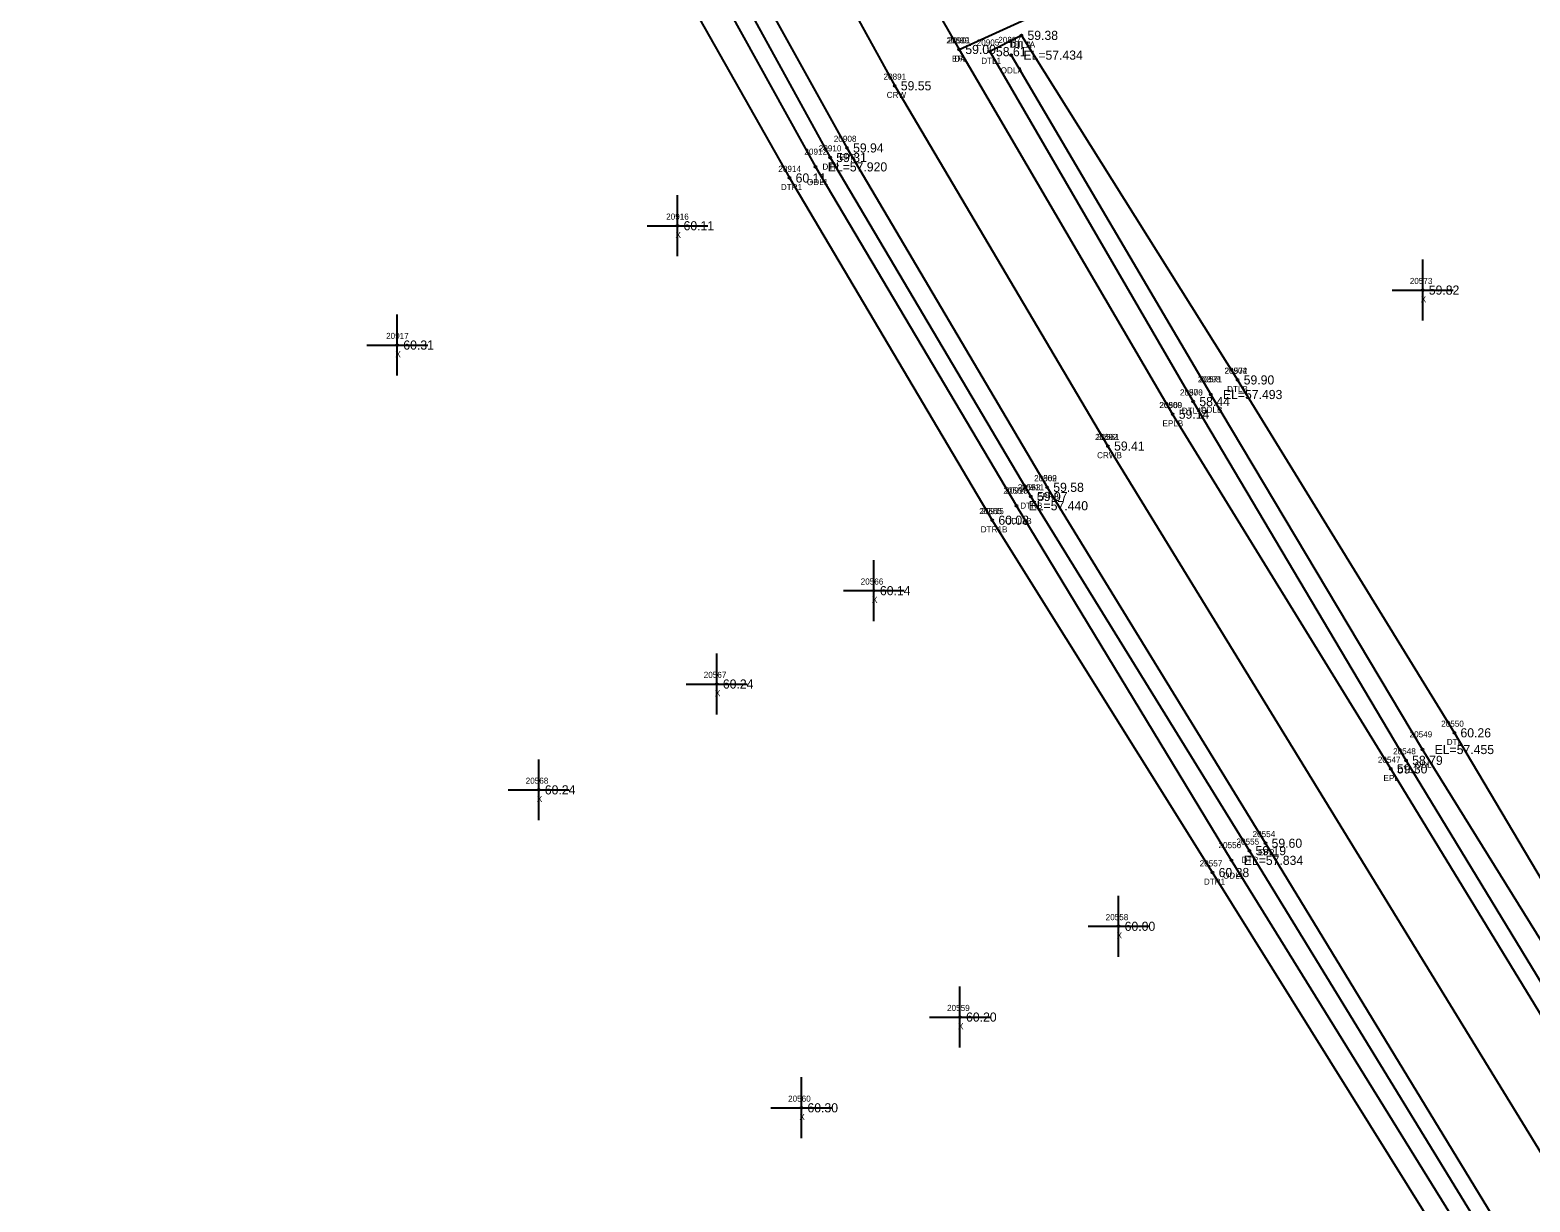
# Model space of a CAD drawing. Extents: x 2396547 to 2397655, y 770185 to 772649.
# Drawn here: x 2397093.2 to 2397339.4, y 770747.4 to 770939.8 of the extents above; entities that cross this region are included whole.
import ezdxf

# ---------------------------------------------------------------- set-up
doc = ezdxf.new("R2010")
doc.units = 0
for name, color, linetype in [('RD_DTM_BkLn1', 7, 'Continuous'), ('RD_EX_Driveway', 7, 'Continuous'), ('RD_EX_Driveway_txCode', 7, 'Continuous'), ('RD_EX_H2O', 7, 'Continuous'), ('RD_EX_H2O_txCode', 7, 'Continuous'), ('RD_EX_Misc', 7, 'Continuous'), ('RD_EX_Misc_txCode', 7, 'Continuous'), ('RD_EX_Road', 7, 'Continuous'), ('RD_EX_Road_txCode', 7, 'Continuous'), ('RD_EX_TX_Driveway_ELEV', 7, 'Continuous'), ('RD_EX_TX_H2O_ELEV', 7, 'Continuous'), ('RD_EX_TX_Misc_ELEV', 7, 'Continuous'), ('RD_EX_TX_Road_ELEV', 7, 'Continuous'), ('RD_HC_Survey_ELEV', 7, 'Continuous'), ('RD_HC_Survey_txCode', 7, 'Continuous'), ('RD_SMD_Locator', 7, 'Continuous')]:
    doc.layers.add(name, color=color, linetype=linetype)

msp = doc.modelspace()

# ---------------------------------------------------------------- linework, layer by layer
at = {"layer": 'RD_DTM_BkLn1'}
for points in [[(2397104.78, 771217.07), (2397119.02, 771175.87), (2397143.13, 771113.88), (2397170.45, 771052.64), (2397197.01, 770999.9), (2397235.12, 770930.63), (2397270.14, 770871.5)], [(2397565.46, 770206.19), (2397547.69, 770280.33), (2397528.11, 770352.94), (2397504.84, 770424.66), (2397476.69, 770499.34), (2397447.19, 770566.69), (2397412.23, 770635.13), (2397363.03, 770719.95), (2397270.14, 770871.5)]]:
    msp.add_lwpolyline(points, dxfattribs=at)
at = {"layer": 'RD_EX_Driveway'}
msp.add_line((2397245.72, 770936.59), (2397279.64, 770952.05), dxfattribs=at)
at = {"layer": 'RD_EX_H2O'}
for p, q in [((2397255.92, 770938.9), (2397291.42, 770882.36)), ((2397254.25, 770935.66), (2397287.01, 770879.96))]:
    msp.add_line(p, q, dxfattribs=at)
for points in [[(2397108.85, 771101.86), (2397130.27, 771108.67), (2397157.99, 771046.03), (2397184.53, 770991.63), (2397224.53, 770918.86), (2397257.48, 770863.23)], [(2397126.28, 771104.16), (2397151.7, 771043.04), (2397181.8, 770990.14), (2397222.13, 770917.32), (2397255.11, 770861.71)], [(2397108.85, 771101.86), (2397123.52, 771093.58), (2397147.97, 771040.86), (2397177.5, 770986.79), (2397217.86, 770915.5), (2397251.15, 770859.33)], [(2397255.92, 770938.9), (2397250.75, 770936.23), (2397284.14, 770878.8)], [(2397586.15, 770211.51), (2397567.31, 770287.61), (2397548.79, 770357.79), (2397525.19, 770434.22), (2397495.53, 770510.39), (2397465.51, 770576.5), (2397430.55, 770645.5), (2397380.29, 770734.7), (2397327.01, 770824.44), (2397291.42, 770882.36)], [(2397579.43, 770209.93), (2397561.1, 770285.3), (2397543.19, 770356.19), (2397518.98, 770431.67), (2397489.88, 770507.8), (2397460.56, 770573.86), (2397425.02, 770642.83), (2397373.6, 770730.3), (2397319.08, 770819.92), (2397284.14, 770878.8)], [(2397583.73, 770210.91), (2397565.2, 770287.05), (2397546.34, 770357.13), (2397522.25, 770433.23), (2397493.26, 770509.76), (2397463.19, 770575.43), (2397428.34, 770644.33), (2397377.24, 770732.42), (2397321.77, 770821.7), (2397287.01, 770879.96)], [(2397428.38, 770563.87), (2397397.36, 770626.2), (2397348.29, 770710.09), (2397290.43, 770803.51), (2397255.11, 770861.71)], [(2397432.83, 770561.85), (2397399.16, 770627.27), (2397350.75, 770711.42), (2397293.36, 770805.09), (2397257.48, 770863.23)], [(2397432.83, 770561.85), (2397426.86, 770559.56), (2397394.23, 770624.59), (2397345.55, 770708.21), (2397287.31, 770801.51), (2397251.15, 770859.33)]]:
    msp.add_lwpolyline(points, dxfattribs=at)
at = {"layer": 'RD_EX_Misc'}
for p, q in [((2397199.46, 770902.66), (2397199.46, 770912.66)), ((2397194.46, 770907.66), (2397204.46, 770907.66)), ((2397321.81, 770892.1), (2397321.81, 770902.1)), ((2397316.81, 770897.1), (2397326.81, 770897.1)), ((2397153.45, 770883.08), (2397153.45, 770893.08)), ((2397148.45, 770888.08), (2397158.45, 770888.08)), ((2397231.7, 770842.77), (2397231.7, 770852.77)), ((2397226.7, 770847.77), (2397236.7, 770847.77)), ((2397205.91, 770827.45), (2397205.91, 770837.45)), ((2397200.91, 770832.45), (2397210.91, 770832.45)), ((2397176.68, 770810.08), (2397176.68, 770820.08)), ((2397171.68, 770815.08), (2397181.68, 770815.08)), ((2397271.88, 770787.69), (2397271.88, 770797.69)), ((2397266.88, 770792.69), (2397276.88, 770792.69)), ((2397245.84, 770772.79), (2397245.84, 770782.79)), ((2397240.84, 770777.79), (2397250.84, 770777.79)), ((2397219.8, 770757.9), (2397219.8, 770767.9)), ((2397214.8, 770762.9), (2397224.8, 770762.9))]:
    msp.add_line(p, q, dxfattribs=at)
at = {"layer": 'RD_EX_Road'}
for points in [[(2397113.76, 771228.75), (2397130.87, 771177.98), (2397154.19, 771118.49), (2397170.38, 771081.25), (2397178.53, 771063.49), (2397207.96, 771004.56), (2397238.54, 770949.11), (2397245.72, 770936.59), (2397280.76, 770876.73)], [(2397093.16, 771212.62), (2397108.35, 771171.65), (2397122.66, 771133.29), (2397131.66, 771109.5), (2397159.86, 771046.96), (2397187.02, 770992.86), (2397227.29, 770920.43), (2397260.16, 770864.73)], [(2397576.88, 770209.21), (2397558.85, 770284.47), (2397539.93, 770354.87), (2397515.81, 770430.13), (2397486.97, 770506.75), (2397457.82, 770572.7), (2397422.37, 770641.75), (2397371.16, 770729.12), (2397316.57, 770818.52), (2397280.76, 770876.73)], [(2397553.19, 770205.48), (2397535.12, 770280.96), (2397517, 770349.24), (2397493.4, 770422.78), (2397467.13, 770492.9), (2397441.16, 770551.74), (2397436.66, 770561.67), (2397402.21, 770629.28), (2397353, 770712.83), (2397296, 770806.32), (2397260.16, 770864.73)]]:
    msp.add_lwpolyline(points, dxfattribs=at)
at = {"layer": 'RD_SMD_Locator'}
for centre in [(2397255.92, 770938.9), (2397255.92, 770938.9), (2397245.72, 770936.59), (2397245.72, 770936.59), (2397250.75, 770936.23), (2397254.25, 770935.66), (2397235.12, 770930.63), (2397227.29, 770920.43), (2397224.53, 770918.86), (2397217.86, 770915.5), (2397222.13, 770917.32), (2397199.46, 770907.66), (2397321.81, 770897.1), (2397153.45, 770888.08), (2397291.42, 770882.36), (2397291.42, 770882.36), (2397284.14, 770878.8), (2397284.14, 770878.8), (2397287.01, 770879.96), (2397287.01, 770879.96), (2397280.76, 770876.73), (2397280.76, 770876.73), (2397270.14, 770871.5), (2397270.14, 770871.5), (2397260.16, 770864.73), (2397260.16, 770864.73), (2397255.11, 770861.71), (2397255.11, 770861.71), (2397257.48, 770863.23), (2397257.48, 770863.23), (2397251.15, 770859.33), (2397251.15, 770859.33), (2397231.7, 770847.77), (2397205.91, 770832.45), (2397327.01, 770824.44), (2397321.77, 770821.7), (2397319.08, 770819.92), (2397316.57, 770818.52), (2397176.68, 770815.08), (2397293.36, 770805.09), (2397296, 770806.32), (2397290.43, 770803.51), (2397287.31, 770801.51), (2397271.88, 770792.69), (2397245.84, 770777.79), (2397219.8, 770762.9)]:
    msp.add_circle(centre, 0.15, dxfattribs=at)

# ---------------------------------------------------------------- texts
at = {"layer": 'RD_EX_Driveway_txCode'}
for s, p in [('20901', (2397243.85, 770937.59)), ('DA', (2397244.93, 770934.59))]:
    msp.add_text(s, height=1, dxfattribs=at).set_placement(p)
at = {"layer": 'RD_EX_H2O_txCode'}
for s, p in [('20905', (2397248.59, 770937.23)), ('20897', (2397252.13, 770937.66)), ('DTL1A', (2397254.02, 770936.9)), ('DTLA', (2397254.19, 770936.9)), ('DTL1', (2397249.34, 770934.23)), ('ODLA', (2397252.52, 770932.66)), ('20912', (2397220.3, 770919.32)), ('20910', (2397222.66, 770919.86)), ('DTR', (2397223.26, 770916.86)), ('20914', (2397216.02, 770916.5)), ('DTR1', (2397216.43, 770913.5)), ('ODL1', (2397220.72, 770914.32)), ('20904', (2397289.26, 770883.36)), ('20572', (2397289.3, 770883.36)), ('20898', (2397284.89, 770881.96)), ('20571', (2397285.17, 770881.96)), ('DTLB', (2397289.7, 770880.36)), ('DTLB', (2397289.7, 770880.36)), ('20906', (2397281.96, 770879.8)), ('20570', (2397281.98, 770879.8)), ('DTL1B', (2397282.26, 770876.8)), ('DTL1B', (2397282.26, 770876.8)), ('ODLB', (2397285.29, 770876.96)), ('ODLB', (2397285.29, 770876.96)), ('20564', (2397252.97, 770863.71)), ('20913', (2397253.27, 770863.71)), ('20563', (2397255.34, 770864.23)), ('20911', (2397255.93, 770864.23)), ('20565', (2397249.01, 770860.33)), ('20915', (2397249.32, 770860.33)), ('DTRB', (2397255.74, 770861.23)), ('DTRB', (2397255.74, 770861.23)), ('ODL1B', (2397253.23, 770858.71)), ('ODL1B', (2397253.23, 770858.71)), ('DTR1B', (2397249.25, 770857.33)), ('DTR1B', (2397249.25, 770857.33)), ('20549', (2397319.66, 770823.7)), ('20550', (2397324.85, 770825.44)), ('20548', (2397316.96, 770820.92)), ('DTL', (2397325.76, 770822.44)), ('ODL', (2397320.53, 770818.7)), ('DTL1', (2397317.67, 770817.92)), ('20555', (2397291.24, 770806.09)), ('20556', (2397288.29, 770805.51)), ('20557', (2397285.19, 770802.51)), ('DTR', (2397292.09, 770803.09)), ('DTR1', (2397285.88, 770799.51)), ('ODL1', (2397289.02, 770800.51))]:
    msp.add_text(s, height=1, dxfattribs=at).set_placement(p)
at = {"layer": 'RD_EX_Misc_txCode'}
for s, p in [('20916', (2397197.6, 770908.66)), ('X', (2397199.14, 770905.66)), ('20573', (2397319.69, 770898.1)), ('X', (2397321.49, 770895.1)), ('20917', (2397151.62, 770889.08)), ('X', (2397153.14, 770886.08)), ('20566', (2397229.54, 770848.77)), ('X', (2397231.39, 770845.77)), ('20567', (2397203.77, 770833.45)), ('X', (2397205.6, 770830.45)), ('20568', (2397174.54, 770816.08)), ('X', (2397176.37, 770813.08)), ('20558', (2397269.76, 770793.69)), ('X', (2397271.56, 770790.69)), ('20559', (2397243.72, 770778.79)), ('X', (2397245.52, 770775.79)), ('20560', (2397217.62, 770763.9)), ('X', (2397219.48, 770760.9))]:
    msp.add_text(s, height=1, dxfattribs=at).set_placement(p)
at = {"layer": 'RD_EX_Road_txCode'}
for s, p in [('20899', (2397243.61, 770937.59)), ('EPL', (2397244.52, 770934.59)), ('20908', (2397225.13, 770921.43)), ('EPR', (2397226.06, 770918.43)), ('20900', (2397278.56, 770877.73)), ('20569', (2397278.61, 770877.73)), ('EPLB', (2397279.08, 770874.73)), ('EPLB', (2397279.08, 770874.73)), ('20909', (2397258.01, 770865.73)), ('20562', (2397258.02, 770865.73)), ('EPRB', (2397258.46, 770862.73)), ('EPRB', (2397258.46, 770862.73)), ('20547', (2397314.45, 770819.52)), ('EPL', (2397315.37, 770816.52)), ('20554', (2397293.88, 770807.32)), ('EPR', (2397294.77, 770804.32))]:
    msp.add_text(s, height=1, dxfattribs=at).set_placement(p)
at = {"layer": 'RD_EX_TX_Driveway_ELEV'}
msp.add_text('59.00', height=1.5, dxfattribs=at).set_placement((2397246.72, 770935.84))
at = {"layer": 'RD_EX_TX_H2O_ELEV'}
for s, p in [('59.38', (2397256.92, 770938.15)), ('59.38', (2397256.92, 770938.15)), ('58.61', (2397251.75, 770935.48)), ('EL=57.434', (2397256.25, 770934.91)), ('EL=57.920', (2397224.13, 770916.57)), ('59.31', (2397225.53, 770918.11)), ('60.11', (2397218.86, 770914.75)), ('59.90', (2397292.42, 770881.61)), ('59.90', (2397292.42, 770881.61)), ('58.44', (2397285.14, 770878.05)), ('58.44', (2397285.14, 770878.05)), ('EL=57.493', (2397289.01, 770879.21)), ('EL=57.493', (2397289.01, 770879.21)), ('59.07', (2397258.48, 770862.48)), ('59.07', (2397258.48, 770862.48)), ('EL=57.440', (2397257.11, 770860.96)), ('EL=57.440', (2397257.11, 770860.96)), ('60.08', (2397252.15, 770858.58)), ('60.08', (2397252.15, 770858.58)), ('60.26', (2397328.01, 770823.69)), ('EL=57.455', (2397323.77, 770820.95)), ('58.79', (2397320.08, 770819.17)), ('59.19', (2397294.36, 770804.34)), ('60.28', (2397288.31, 770800.76)), ('EL=57.834', (2397292.43, 770802.76))]:
    msp.add_text(s, height=1.5, dxfattribs=at).set_placement(p)
at = {"layer": 'RD_EX_TX_Misc_ELEV'}
for s, p in [('60.11', (2397200.46, 770906.91)), ('59.82', (2397322.81, 770896.35)), ('60.31', (2397154.45, 770887.33)), ('60.14', (2397232.7, 770847.02)), ('60.24', (2397206.91, 770831.7)), ('60.24', (2397177.68, 770814.33)), ('60.00', (2397272.88, 770791.94)), ('60.20', (2397246.84, 770777.04)), ('60.30', (2397220.8, 770762.15))]:
    msp.add_text(s, height=1.5, dxfattribs=at).set_placement(p)
at = {"layer": 'RD_EX_TX_Road_ELEV'}
for s, p in [('59.00', (2397246.72, 770935.84)), ('59.94', (2397228.29, 770919.68)), ('59.14', (2397281.76, 770875.98)), ('59.14', (2397281.76, 770875.98)), ('59.58', (2397261.16, 770863.98)), ('59.58', (2397261.16, 770863.98)), ('59.30', (2397317.57, 770817.77)), ('59.60', (2397297, 770805.57))]:
    msp.add_text(s, height=1.5, dxfattribs=at).set_placement(p)
at = {"layer": 'RD_HC_Survey_ELEV'}
for s, p in [('59.55', (2397236.12, 770929.88)), ('59.41', (2397271.14, 770870.75)), ('59.41', (2397271.14, 770870.75))]:
    msp.add_text(s, height=1.5, dxfattribs=at).set_placement(p)
at = {"layer": 'RD_HC_Survey_txCode'}
for s, p in [('20891', (2397233.29, 770931.63)), ('CRW', (2397233.81, 770928.63)), ('20892', (2397268.02, 770872.5)), ('20561', (2397268.28, 770872.5)), ('CRWB', (2397268.35, 770869.5)), ('CRWB', (2397268.35, 770869.5))]:
    msp.add_text(s, height=1, dxfattribs=at).set_placement(p)

doc.saveas('drawing.dxf')
